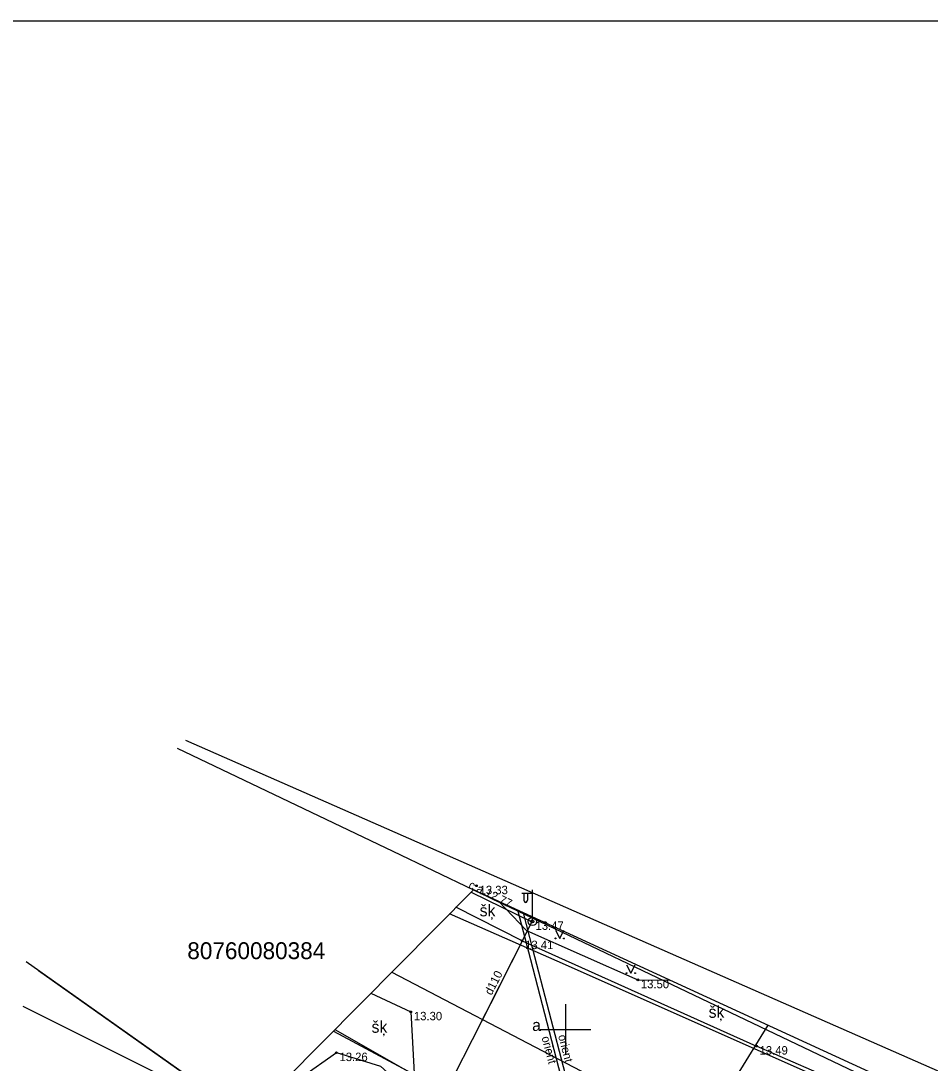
# Model space of a CAD drawing. Extents: x 503904 to 504094, y 304688 to 304960.
# Drawn here: x 503967.7 to 504021.6, y 304898 to 304959.8 of the extents above; entities that cross this region are included whole.
import ezdxf

# ---------------------------------------------------------------- set-up
doc = ezdxf.new("R2010")
doc.units = 0
for name, color, linetype in [('APGR_SARK_####_####_#', 7, 'Continuous'), ('APGS_ACRL_####_####_#', 7, 'Continuous'), ('APGS_ACRL_####_TKST_#', 7, 'Continuous'), ('APGS_ELEM_####_####_#', 7, 'Continuous'), ('APGS_VADP_ZSPR_####_#', 7, 'Continuous'), ('CELI_CMAL_####_####_#', 7, 'Continuous'), ('CELI_CSEG_####_TKST_#', 7, 'Continuous'), ('CELI_TAKA_####_####_#', 7, 'Continuous'), ('ELEK_ACRL_####_####_#', 7, 'Continuous'), ('ELEK_VADP_ZSPR_####_#', 7, 'Continuous'), ('ELEK_VADP_ZSPR_TKST_#', 7, 'Continuous'), ('GAZE_VADP_VSP2_####_#', 7, 'Continuous'), ('GEOD_ELEM_####_####_#', 7, 'Continuous'), ('RAMI_PLAN_####_TKST_#', 7, 'Continuous'), ('RAMI_UZMR_####_####_#', 7, 'Continuous'), ('RELJ_AATZ_####_TKST_#', 7, 'Continuous'), ('RELJ_ELEM_####_####_#', 7, 'Continuous'), ('ROBZ_UZMR_####_####_#', 7, 'Continuous'), ('ROBZ_UZMR_####_TKST_#', 7, 'Continuous'), ('SAKK_KKAN_####_####_#', 7, 'Continuous'), ('TERT_ELEM_####_####_#', 7, 'Continuous'), ('UDTK_VADP_UDEN_####_#', 7, 'Continuous')]:
    doc.layers.add(name, color=color, linetype=linetype)

msp = doc.modelspace()

# ---------------------------------------------------------------- linework, layer by layer
at = {"layer": 'APGR_SARK_####_####_#'}
for p, q in [((503977.453, 304917.18), (504048.875, 304885.773)), ((503967.818, 304901.39), (503981.123, 304894.75))]:
    msp.add_line(p, q, dxfattribs=at)
at = {"layer": 'APGS_ACRL_####_####_#'}
for points in [[(503994.396, 304908.162), (503998.01, 304906.396)], [(503997.708, 304905.8), (503994.46, 304899.393), (503993.378, 304897.257), (503993.361, 304897.025), (503993.516, 304896.851), (503996.758, 304895.298), (503998.379, 304894.525), (504000, 304893.745), (504003.241, 304892.193)]]:
    msp.add_lwpolyline(points, dxfattribs=at)
at = {"layer": 'APGS_ELEM_####_####_#'}
for p, q in [((503998.036, 304906.418), (503998.036, 304908.301)), ((503998.036, 304908.085), (503997.401, 304908.08)), ((503997.536, 304908.081), (503997.536, 304907.689)), ((503997.746, 304908.083), (503997.746, 304907.689))]:
    msp.add_line(p, q, dxfattribs=at)
for radius in [0.25, 0.09]:
    msp.add_circle((503998.036, 304906.418), radius, dxfattribs=at)
msp.add_ellipse((503997.641, 304907.689), major_axis=(0, 0.151), ratio=0.695971, start_param=1.570796, end_param=4.712389, dxfattribs=at)
at = {"layer": 'APGS_VADP_ZSPR_####_#'}
msp.add_lwpolyline([(503994.396, 304908.162), (503998.01, 304906.396), (503995.543, 304901.529), (503993.378, 304897.257), (503993.361, 304897.025), (503993.516, 304896.85), (503996.758, 304895.3), (504000, 304893.749), (504004.081, 304891.797), (504008.162, 304889.845), (504008.322, 304889.653), (504008.281, 304889.406), (504007.328, 304888.005), (504006.375, 304886.604), (504006.058, 304885.968)], dxfattribs=at)
at = {"layer": 'CELI_CMAL_####_####_#'}
msp.add_line((503997.42, 304905.277), (503993.501, 304907.257), dxfattribs=at)
for points in [[(503997.42, 304905.277), (504011.327, 304899.02)], [(503988.454, 304902.158), (503990.823, 304901.054), (503991.097, 304895.946), (503989.732, 304890.943), (503987.103, 304886.103), (503981.039, 304876.47), (503973.971, 304864.108), (503962.412, 304839.295), (503956.935, 304827.255), (503950.616, 304813.727), (503945.51, 304803.343), (503951.501, 304800.629), (503951.721, 304801.18), (503956.987, 304798.767), (503955.478, 304795.066), (503959.037, 304792.215), (503963.727, 304789.581), (503971.677, 304784.658)], [(504056.369, 304885.722), (504054.86, 304884.787), (504047.246, 304885.659), (504038.184, 304887.536), (504028.058, 304891.478), (504020.037, 304895.213), (504011.327, 304899.02)]]:
    msp.add_lwpolyline(points, dxfattribs=at)
at = {"layer": 'CELI_TAKA_####_####_#'}
for points in [[(503996.022, 304907.619), (503997.681, 304905.878), (504004.285, 304902.953), (504006.195, 304902.938)], [(503981.42, 304894.481), (503982.27, 304895.717), (503986.409, 304898.633), (503989.03, 304897.84), (503991.097, 304895.946)]]:
    msp.add_lwpolyline(points, dxfattribs=at)
at = {"layer": 'ELEK_ACRL_####_####_#'}
msp.add_lwpolyline([(503986.232, 304899.912), (504002.69, 304891.089)], dxfattribs=at)
at = {"layer": 'ELEK_VADP_ZSPR_####_#'}
for points in [[(503997.15, 304907.1), (503997.915, 304904.16), (504000, 304896.148), (504001.196, 304891.552), (504002.392, 304886.957)], [(504002.77, 304886.696), (504000, 304897.339), (503998.067, 304904.766), (503997.502, 304906.938)], [(504012.009, 304900.262), (504010.129, 304897.225), (504006.795, 304891.841)], [(503986.232, 304899.912), (504000, 304892.531), (504005.246, 304889.719), (504005.346, 304889.587), (504005.312, 304889.424), (504004.381, 304888.161)]]:
    msp.add_lwpolyline(points, dxfattribs=at)
at = {"layer": 'GAZE_VADP_VSP2_####_#'}
msp.add_lwpolyline([(503989.698, 304903.414), (504000, 304898.037), (504010.212, 304892.707), (504011.048, 304889.414), (504011.884, 304886.121), (504025.295, 304879.492), (504038.706, 304872.862), (504042.754, 304870.726), (504047.158, 304868.745), (504052.063, 304869.587)], dxfattribs=at)
at = {"layer": 'GEOD_ELEM_####_####_#'}
for p, q in [((504000, 304901.5), (504000, 304900)), ((503998.5, 304900), (504000, 304900)), ((504000, 304900), (504000, 304898.5)), ((504000, 304900), (504001.5, 304900))]:
    msp.add_line(p, q, dxfattribs=at)
at = {"layer": 'RAMI_PLAN_####_TKST_#'}
msp.add_lwpolyline([(503904.204, 304959.85), (504093.703, 304959.85), (504093.703, 304823.741), (503904.204, 304823.741)], close=True, dxfattribs=at)
at = {"layer": 'RAMI_UZMR_####_####_#'}
msp.add_lwpolyline([(503923.253, 304801.015), (503981.982, 304759.672), (503995.48, 304748.813), (504027.75, 304817.255), (504060.02, 304885.696), (504048.875, 304885.773), (504036.803, 304888.853), (503994.536, 304908.303), (503981.123, 304894.75), (503978.518, 304892.436), (503950.886, 304846.726), (503923.253, 304801.015)], dxfattribs=at)
at = {"layer": 'RELJ_ELEM_####_####_#'}
for centre in [(503994.72, 304908.534), (503997.42, 304905.277), (504004.285, 304902.953), (503990.823, 304901.054), (504011.327, 304899.02), (503986.409, 304898.633)]:
    msp.add_circle(centre, 0.05, dxfattribs=at)
at = {"layer": 'ROBZ_UZMR_####_####_#'}
for points in [[(503976.959, 304916.696), (503989.759, 304910.584), (503994.536, 304908.303), (504011.531, 304900.187), (504020.191, 304896.051), (504036.803, 304888.853), (504048.875, 304885.773), (504074.124, 304885.169)], [(504052.953, 304844.812), (504048.85, 304847.4), (504030.463, 304860.121), (503981.123, 304894.75), (503968.011, 304904.031)], [(503968.744, 304903.512), (503981.123, 304894.75), (503978.518, 304892.436), (503923.29, 304801.044), (503917.762, 304804.94)]]:
    msp.add_lwpolyline(points, dxfattribs=at)
at = {"layer": 'SAKK_KKAN_####_####_#'}
msp.add_lwpolyline([(503986.316, 304899.997), (504000, 304892.196), (504013.782, 304884.178), (504021.554, 304879.802), (504033.218, 304873.459), (504039.007, 304870.064), (504043.395, 304867.859), (504047.782, 304865.655), (504048.401, 304866.822), (504050.758, 304867.21)], dxfattribs=at)
at = {"layer": 'TERT_ELEM_####_####_#'}
for p, q in [((503999.407, 304905.909), (503999.657, 304905.409)), ((503999.657, 304905.409), (503999.907, 304905.909)), ((504003.628, 304903.85), (504003.878, 304903.35)), ((504003.878, 304903.35), (504004.128, 304903.85))]:
    msp.add_line(p, q, dxfattribs=at)
for centre, radius in [((503999.407, 304905.408), 0.028), ((503999.907, 304905.408), 0.0263), ((504003.627, 304903.35), 0.028), ((504004.127, 304903.35), 0.0263)]:
    msp.add_circle(centre, radius, dxfattribs=at)
at = {"layer": 'UDTK_VADP_UDEN_####_#'}
msp.add_lwpolyline([(504059.328, 304884.23), (504052.534, 304884.693), (504043.033, 304885.34), (504032.956, 304889.369), (504014.268, 304897.491), (504000, 304903.846), (503993.127, 304906.879)], dxfattribs=at)

# ---------------------------------------------------------------- texts
at = {"layer": 'APGS_ACRL_####_TKST_#'}
for s, rotation, p in [('c.a.12.77', 333.96365, (503994.202, 304908.423)), ('d110', 63.12173, (503995.616, 304902.005))]:
    msp.add_text(s, height=0.5, rotation=rotation, dxfattribs=at).set_placement(p)
at = {"layer": 'CELI_CSEG_####_TKST_#'}
for s, p in [('šķ', (503994.907, 304906.72)), ('šķ', (504008.49, 304900.7)), ('šķ', (503988.496, 304899.813)), ('a', (503998.021, 304899.918))]:
    msp.add_text(s, height=0.7, dxfattribs=at).set_placement(p)
at = {"layer": 'ELEK_VADP_ZSPR_TKST_#'}
for p in [(503998.578, 304899.542), (503999.558, 304899.633)]:
    msp.add_text('orient', height=0.5, rotation=284.58792, dxfattribs=at).set_placement(p)
at = {"layer": 'RELJ_AATZ_####_TKST_#'}
for s, p in [(' 13.33', (503994.72, 304908.034)), (' 13.47', (503998.036, 304905.918)), (' 13.41', (503997.42, 304904.777)), (' 13.50', (504004.285, 304902.453)), (' 13.30', (503990.823, 304900.554)), (' 13.49', (504011.327, 304898.52)), (' 13.26', (503986.409, 304898.133))]:
    msp.add_text(s, height=0.5, dxfattribs=at).set_placement(p)
at = {"layer": 'ROBZ_UZMR_####_TKST_#'}
msp.add_text('80760080384', height=1, dxfattribs=at).set_placement((503977.568, 304904.182))

doc.saveas('drawing.dxf')
